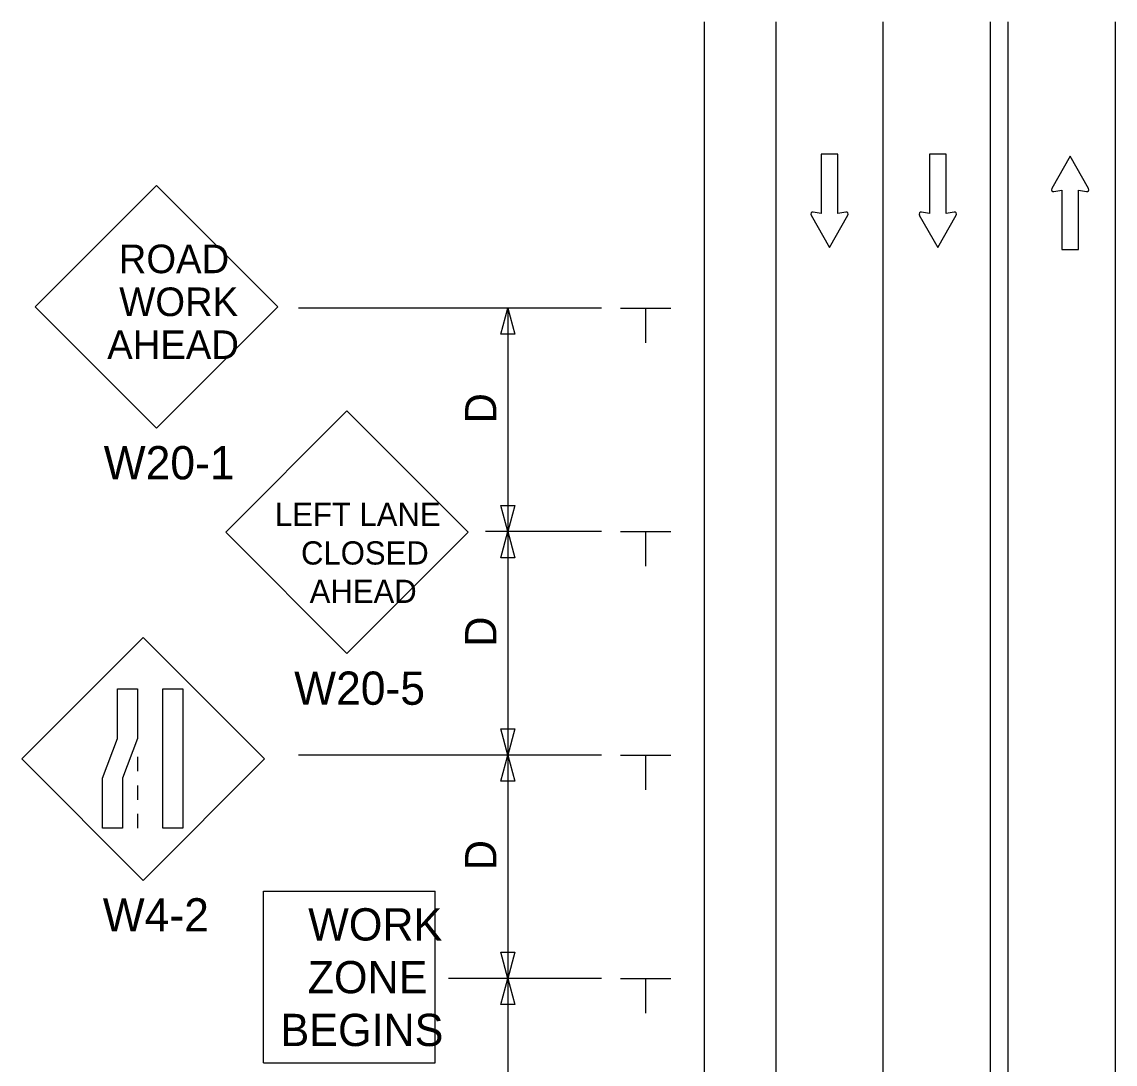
# Model space of a CAD drawing. Extents: x 16796 to 18475, y 7218 to 8209.
# Drawn here: x 16816.5 to 17061.3, y 7971.7 to 8204.9 of the extents above; entities that cross this region are included whole.
import ezdxf

# ---------------------------------------------------------------- set-up
doc = ezdxf.new("R2010")
doc.units = 0
for name, color, linetype in [('ALI_LEGAL_EX', 7, 'Continuous'), ('MT_SCRATCH_LEVEL_E', 7, 'Continuous'), ('PAVT_EDGE_EX', 7, 'Continuous'), ('TRAFFIC_SIGNS_PR', 7, 'Continuous'), ('TYPICAL_TEXT_DIMEN_PR', 7, 'Continuous')]:
    doc.layers.add(name, color=color, linetype=linetype)

msp = doc.modelspace()

# ---------------------------------------------------------------- linework, layer by layer
at = {"layer": 'ALI_LEGAL_EX'}
for p, q in [((17009.33, 8204.89), (17009.33, 7353.77)), ((17061.33, 8204.89), (17061.33, 7353.77))]:
    msp.add_line(p, q, dxfattribs=at)
for points in [[(17009.33, 8204.89), (17009.33, 8179.89)], [(17061.33, 8204.89), (17061.33, 8179.89)], [(17009.33, 8104.89), (17009.33, 8079.89)], [(17061.33, 8104.89), (17061.33, 8079.89)], [(17009.33, 8004.89), (17009.33, 7979.89)], [(17061.33, 8004.89), (17061.33, 7979.89)]]:
    msp.add_lwpolyline(points, dxfattribs=at)
at = {"layer": 'MT_SCRATCH_LEVEL_E'}
for p, q in [((16999.25, 8175.26), (16995.51, 8175.26)), ((16995.51, 8175.26), (16995.51, 8162)), ((16999.25, 8175.26), (16995.51, 8175.26)), ((16995.51, 8175.26), (16995.51, 8162)), ((16999.25, 8162), (16999.25, 8175.26)), ((16999.25, 8162), (16999.25, 8175.26)), ((17023.49, 8175.26), (17019.74, 8175.26)), ((17019.74, 8175.26), (17019.74, 8162)), ((17023.49, 8175.26), (17019.74, 8175.26)), ((17019.74, 8175.26), (17019.74, 8162)), ((17023.49, 8162), (17023.49, 8175.26)), ((17023.49, 8162), (17023.49, 8175.26)), ((17051.25, 8174.82), (17047.14, 8167.58)), ((17051.25, 8174.82), (17047.14, 8167.58)), ((17055.4, 8167.58), (17051.25, 8174.82)), ((17055.4, 8167.58), (17051.25, 8174.82)), ((17047.62, 8166.9), (17049.4, 8167.22)), ((17047.62, 8166.9), (17049.4, 8167.22)), ((17049.4, 8167.22), (17049.4, 8153.96)), ((17049.4, 8167.22), (17049.4, 8153.96)), ((17053.14, 8153.96), (17053.14, 8167.22)), ((17053.14, 8167.22), (17054.92, 8166.9)), ((17053.14, 8153.96), (17053.14, 8167.22)), ((17053.14, 8167.22), (17054.92, 8166.9)), ((16993.25, 8161.63), (16997.4, 8154.39)), ((16993.25, 8161.63), (16997.4, 8154.39)), ((16995.51, 8162), (16993.73, 8162.32)), ((16995.51, 8162), (16993.73, 8162.32)), ((16997.4, 8154.39), (17001.51, 8161.63)), ((16997.4, 8154.39), (17001.51, 8161.63)), ((17001.03, 8162.32), (16999.25, 8162)), ((17001.03, 8162.32), (16999.25, 8162)), ((17017.49, 8161.63), (17021.63, 8154.39)), ((17017.49, 8161.63), (17021.63, 8154.39)), ((17019.74, 8162), (17017.97, 8162.32)), ((17019.74, 8162), (17017.97, 8162.32)), ((17021.63, 8154.39), (17025.74, 8161.63)), ((17021.63, 8154.39), (17025.74, 8161.63)), ((17025.26, 8162.32), (17023.49, 8162)), ((17025.26, 8162.32), (17023.49, 8162)), ((17049.4, 8153.96), (17053.14, 8153.96)), ((17049.4, 8153.96), (17053.14, 8153.96))]:
    msp.add_line(p, q, dxfattribs=at)
for centre, start, end in [((17047.54, 8167.36), 150.4248, 279.9638), ((17047.54, 8167.36), 150.4248, 279.9638), ((17054.99, 8167.36), 260.0362, 29.7731), ((17054.99, 8167.36), 260.0362, 29.7731), ((16993.66, 8161.86), 80.0362, 209.7731), ((16993.66, 8161.86), 80.0362, 209.7731), ((17001.1, 8161.86), 330.4248, 99.9638), ((17001.1, 8161.86), 330.4248, 99.9638), ((17017.9, 8161.86), 80.0362, 209.7731), ((17017.9, 8161.86), 80.0362, 209.7731), ((17025.34, 8161.86), 330.4248, 99.9638), ((17025.34, 8161.86), 330.4248, 99.9638)]:
    msp.add_arc(centre, 0.463, start, end, dxfattribs=at)
at = {"layer": 'PAVT_EDGE_EX'}
for p, q in [((16969.33, 8204.89), (16969.33, 7353.77)), ((16985.33, 8204.89), (16985.33, 7353.77)), ((17033.33, 8204.89), (17033.33, 7836.29)), ((17037.33, 8204.89), (17037.33, 7836.29))]:
    msp.add_line(p, q, dxfattribs=at)
at = {"layer": 'TRAFFIC_SIGNS_PR'}
for p, q in [((16846.7, 8168.26), (16819.55, 8141.11)), ((16873.85, 8141.11), (16846.7, 8168.26)), ((16819.55, 8141.11), (16846.7, 8113.96)), ((16846.7, 8113.96), (16873.85, 8141.11)), ((16889.33, 8117.81), (16862.18, 8090.66)), ((16916.49, 8090.66), (16889.33, 8117.81)), ((16862.18, 8090.66), (16889.33, 8063.51)), ((16889.33, 8063.51), (16916.49, 8090.66)), ((16843.7, 8067.09), (16816.55, 8039.94)), ((16870.85, 8039.94), (16843.7, 8067.09)), ((16816.55, 8039.94), (16843.7, 8012.78)), ((16842.45, 8040.43), (16842.45, 8037.23)), ((16843.7, 8012.78), (16870.85, 8039.94)), ((16842.45, 8034.03), (16842.45, 8030.83)), ((16842.45, 8027.63), (16842.45, 8024.43)), ((16870.65, 7971.95), (16870.65, 8010.35)), ((16870.65, 8010.35), (16909.05, 8010.35)), ((16909.05, 7971.95), (16909.05, 8010.35)), ((16870.65, 7971.95), (16909.05, 7971.95))]:
    msp.add_line(p, q, dxfattribs=at)
for points in [[(16842.45, 8055.67), (16842.45, 8044.49), (16839.11, 8035.61), (16839.11, 8024.43), (16834.62, 8024.43), (16834.62, 8035.61), (16837.96, 8044.49), (16837.96, 8055.67)], [(16852.59, 8055.67), (16852.59, 8024.43), (16848.1, 8024.43), (16848.1, 8055.67)]]:
    msp.add_lwpolyline(points, close=True, dxfattribs=at)
at = {"layer": 'TYPICAL_TEXT_DIMEN_PR'}
for p, q in [((16946.33, 8140.83), (16878.51, 8140.83)), ((16923.76, 8134.97), (16925.33, 8140.83)), ((16925.33, 8140.83), (16925.33, 8090.83)), ((16925.33, 8140.83), (16926.9, 8134.97)), ((16950.58, 8140.83), (16961.83, 8140.83)), ((16956.21, 8140.83), (16956.21, 8133.05)), ((16925.33, 8134.97), (16923.76, 8134.97)), ((16926.9, 8134.97), (16925.33, 8134.97)), ((16925.33, 8090.83), (16923.76, 8096.69)), ((16923.76, 8096.69), (16925.33, 8096.69)), ((16925.33, 8096.69), (16926.9, 8096.69)), ((16926.9, 8096.69), (16925.33, 8090.83)), ((16946.33, 8090.83), (16920.33, 8090.83)), ((16923.76, 8084.97), (16925.33, 8090.83)), ((16925.33, 8090.83), (16925.33, 8040.83)), ((16925.33, 8090.83), (16926.9, 8084.97)), ((16950.58, 8090.83), (16961.83, 8090.83)), ((16956.21, 8090.83), (16956.21, 8083.05)), ((16925.33, 8084.97), (16923.76, 8084.97)), ((16926.9, 8084.97), (16925.33, 8084.97)), ((16925.33, 8040.83), (16923.76, 8046.69)), ((16923.76, 8046.69), (16925.33, 8046.69)), ((16925.33, 8046.69), (16926.9, 8046.69)), ((16926.9, 8046.69), (16925.33, 8040.83)), ((16946.33, 8040.83), (16878.51, 8040.83)), ((16923.76, 8034.97), (16925.33, 8040.83)), ((16925.33, 8040.83), (16926.9, 8034.97)), ((16925.33, 8040.83), (16925.33, 7990.83)), ((16950.58, 8040.83), (16961.83, 8040.83)), ((16956.21, 8040.83), (16956.21, 8033.05)), ((16925.33, 8034.97), (16923.76, 8034.97)), ((16926.9, 8034.97), (16925.33, 8034.97)), ((16925.33, 7990.83), (16923.76, 7996.69)), ((16923.76, 7996.69), (16925.33, 7996.69)), ((16925.33, 7996.69), (16926.9, 7996.69)), ((16926.9, 7996.69), (16925.33, 7990.83)), ((16946.33, 7990.83), (16912.09, 7990.83)), ((16923.76, 7984.97), (16925.33, 7990.83)), ((16925.33, 7990.83), (16925.33, 7940.83)), ((16925.33, 7990.83), (16926.9, 7984.97)), ((16950.58, 7990.83), (16961.83, 7990.83)), ((16956.21, 7990.83), (16956.21, 7983.05)), ((16925.33, 7984.97), (16923.76, 7984.97)), ((16926.9, 7984.97), (16925.33, 7984.97))]:
    msp.add_line(p, q, dxfattribs=at)

# ---------------------------------------------------------------- texts
at = {"layer": 'TRAFFIC_SIGNS_PR'}
for s, height, p in [('ROAD', 6.4, (16838.24, 8148.65)), ('WORK', 6.4, (16838.35, 8139.05)), ('AHEAD', 6.4, (16835.66, 8129.45)), ('W20-1', 7.44, (16834.87, 8102.52)), ('LEFT LANE', 5.2, (16873.21, 8092.06)), ('CLOSED', 5.2, (16879.05, 8083.45)), ('AHEAD', 5.2, (16880.99, 8074.86)), ('W20-5', 7.44, (16877.51, 8052.07)), ('W4-2', 7.44, (16834.66, 8001.34)), ('WORK', 7.217, (16880.65, 7999.32)), ('ZONE', 7.217, (16880.54, 7987.51)), ('BEGINS', 7.217, (16874.46, 7975.7))]:
    msp.add_text(s, height=height, dxfattribs=at).set_placement(p)
at = {"layer": 'TYPICAL_TEXT_DIMEN_PR'}
for p in [(16922.78, 8115.05), (16922.78, 8065.05), (16922.78, 8015.05)]:
    msp.add_text('D', height=7, rotation=90, dxfattribs=at).set_placement(p)

doc.saveas('drawing.dxf')
